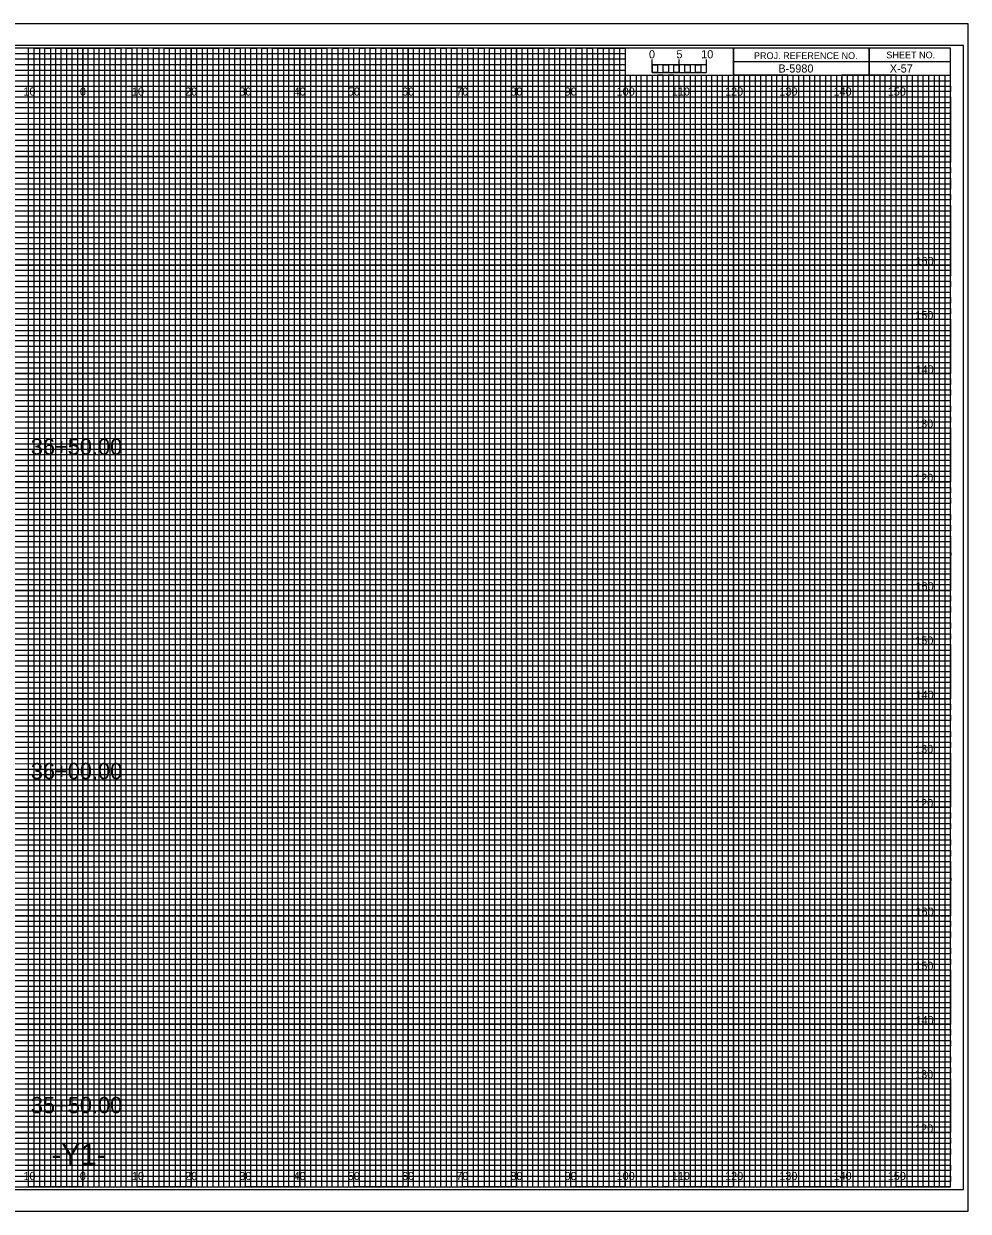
# Model space of a CAD drawing. Extents: x -13 to 323, y -5 to 4834.
# Drawn here: x 149.1 to 323.3, y 2415.5 to 2634.5 of the extents above; entities that cross this region are included whole.
import ezdxf

# ---------------------------------------------------------------- set-up
doc = ezdxf.new("R2010")
doc.units = 0
for name, color, linetype in [('Exist CMT Pavement', 7, 'Continuous'), ('Exist Cross Section Cell', 7, 'Continuous'), ('Exist XS Center Line Elevation Label', 7, 'Continuous'), ('Exist XS Ground Line', 7, 'Continuous'), ('Prop CMT Pvmt Course 1', 7, 'Continuous'), ('Prop CMT Pvmt Course 1 Wedge', 7, 'Continuous'), ('Prop CMT Pvmt Course 2', 7, 'Continuous'), ('Prop CMT Pvmt Course 2 Wedge', 7, 'Continuous'), ('Prop CMT Pvmt Course 3', 7, 'Continuous'), ('Prop CMT Pvmt Course 3 Wedge', 7, 'Continuous'), ('Prop CMT Pvmt Surface', 7, 'Continuous'), ('Prop CMT Pvmt Surface Shoulder', 7, 'Continuous'), ('Prop CMT Shld Paved Course 1', 7, 'Continuous'), ('Prop CMT Shld Paved Course 2', 7, 'Continuous'), ('Prop CMT Shld Paved Course 3', 7, 'Continuous'), ('Prop CMT Slope Grass', 7, 'Continuous'), ('Prop CMT Subgrade Earthwork', 7, 'Continuous')]:
    doc.layers.add(name, color=color, linetype=linetype)

msp = doc.modelspace()

# ---------------------------------------------------------------- linework, layer by layer
at = {"layer": 'Exist XS Center Line Elevation Label'}
for points in [[(145, 2420), (155, 2420), (155, 2630), (165, 2630), (165, 2420), (175, 2420), (175, 2630), (185, 2630), (185, 2420), (195, 2420), (195, 2630), (205, 2630), (205, 2420), (215, 2420), (215, 2630), (225, 2630), (225, 2420), (235, 2420), (235, 2630), (245, 2630), (245, 2420), (255, 2420), (255, 2630), (259.93, 2630), (260, 2630), (260, 2625), (264.99, 2625), (264.99, 2420), (275, 2420), (275, 2625), (285, 2625), (285, 2420), (295, 2420), (295, 2625), (305, 2625), (305, 2420), (315, 2420), (315, 2625)], [(0, 2625), (275, 2625)], [(0, 2605), (320, 2605), (320, 2615), (0, 2615)], [(0, 2585), (320, 2585), (320, 2595), (0, 2595)], [(0, 2565), (320, 2565), (320, 2575), (0, 2575)], [(0, 2545), (320, 2545), (320, 2555), (0, 2555)], [(0, 2525), (320, 2525), (320, 2535), (0, 2535)], [(0, 2505), (320, 2505), (320, 2515), (0, 2515)], [(0, 2485), (320, 2485), (320, 2495), (0, 2495)], [(0, 2465), (320, 2465), (320, 2475), (0, 2475)], [(0, 2445), (320, 2445), (320, 2455), (0, 2455)], [(0, 2425), (320, 2425), (320, 2435), (0, 2435)]]:
    msp.add_lwpolyline(points, dxfattribs=at)
at = {"layer": 'Exist XS Ground Line'}
for p, q in [((150, 2630), (140, 2630)), ((150, 2420), (150, 2630)), ((170, 2630), (160, 2630)), ((160, 2630), (160, 2420)), ((170, 2420), (170, 2630)), ((190, 2630), (180, 2630)), ((180, 2630), (180, 2420)), ((190, 2420), (190, 2630)), ((210, 2630), (200, 2630)), ((200, 2630), (200, 2420)), ((210, 2420), (210, 2630)), ((230, 2630), (220, 2630)), ((220, 2630), (220, 2420)), ((230, 2420), (230, 2630)), ((250, 2630), (240, 2630)), ((240, 2630), (240, 2420)), ((250, 2420), (250, 2630)), ((260, 2630), (260, 2420)), ((270, 2420), (270, 2625)), ((290, 2625), (280, 2625)), ((280, 2625), (280, 2420)), ((290, 2420), (290, 2625)), ((310, 2625), (300, 2625)), ((300, 2625), (300, 2420)), ((310, 2420), (310, 2625)), ((160, 2420), (150, 2420)), ((180, 2420), (170, 2420)), ((200, 2420), (190, 2420)), ((220, 2420), (210, 2420)), ((240, 2420), (230, 2420)), ((260, 2420), (250, 2420)), ((280, 2420), (270, 2420)), ((300, 2420), (290, 2420)), ((320, 2420), (310, 2420)), ((320, 2420), (320, 2420))]:
    msp.add_line(p, q, dxfattribs=at)
for points in [[(0, 2620), (320, 2620), (320, 2610), (0, 2610)], [(0, 2600), (320, 2600), (320, 2590), (0, 2590)], [(0, 2580), (320, 2580), (320, 2570), (0, 2570)], [(0, 2560), (320, 2560), (320, 2550), (0, 2550)], [(0, 2540), (320, 2540), (320, 2530), (0, 2530)], [(0, 2520), (320, 2520), (320, 2510), (0, 2510)], [(0, 2500), (320, 2500), (320, 2490), (0, 2490)], [(0, 2480), (320, 2480), (320, 2470), (0, 2470)], [(0, 2460), (320, 2460), (320, 2450), (0, 2450)], [(0, 2440), (320, 2440), (320, 2430), (0, 2430)]]:
    msp.add_lwpolyline(points, dxfattribs=at)
at = {"layer": 'Prop CMT Pvmt Course 1'}
for p, q in [((267, 2625), (266.01, 2625)), ((266.01, 2625), (266.01, 2420)), ((267, 2420), (267, 2625)), ((269, 2625), (268, 2625)), ((268, 2625), (268, 2420)), ((269, 2420), (269, 2625)), ((266.01, 2420), (265, 2420)), ((268, 2420), (267, 2420))]:
    msp.add_line(p, q, dxfattribs=at)
for points in [[(150, 2420), (151, 2420), (151, 2630), (152, 2630), (152, 2420)], [(152, 2420), (153, 2420), (153, 2630), (154, 2630), (154, 2420)], [(155, 2420), (156, 2420), (156, 2630), (157, 2630), (157, 2420)], [(157, 2420), (158, 2420), (158, 2630), (159, 2630), (159, 2420)], [(160, 2420), (161, 2420), (161, 2630), (162, 2630), (162, 2420)], [(162, 2420), (163, 2420), (163, 2630), (164, 2630), (164, 2420)], [(165, 2420), (166, 2420), (166, 2630), (167, 2630), (167, 2420)], [(167, 2420), (168, 2420), (168, 2630), (169, 2630), (169, 2420)], [(170, 2420), (171, 2420), (171, 2630), (172, 2630), (172, 2420)], [(172, 2420), (173, 2420), (173, 2630), (174, 2630), (174, 2420)], [(175, 2420), (176, 2420), (176, 2630), (177, 2630), (177, 2420)], [(177, 2420), (178, 2420), (178, 2630), (179, 2630), (179, 2420)], [(180, 2420), (181, 2420), (181, 2630), (182, 2630), (182, 2420)], [(182, 2420), (183, 2420), (183, 2630), (184, 2630), (184, 2420)], [(185, 2420), (186, 2420), (186, 2630), (187, 2630), (187, 2420)], [(187, 2420), (188, 2420), (188, 2630), (189, 2630), (189, 2420)], [(190, 2420), (191, 2420), (191, 2630), (192, 2630), (192, 2420)], [(192, 2420), (193, 2420), (193, 2630), (194, 2630), (194, 2420)], [(195, 2420), (196, 2420), (196, 2630), (197, 2630), (197, 2420)], [(197, 2420), (198, 2420), (198, 2630), (199, 2630), (199, 2420)], [(200, 2420), (201, 2420), (201, 2630), (202, 2630), (202, 2420)], [(202, 2420), (203, 2420), (203, 2630), (204, 2630), (204, 2420)], [(205, 2420), (206, 2420), (206, 2630), (207, 2630), (207, 2420)], [(207, 2420), (208, 2420), (208, 2630), (209, 2630), (209, 2420)], [(210, 2420), (211, 2420), (211, 2630), (212, 2630), (212, 2420)], [(212, 2420), (213, 2420), (213, 2630), (214, 2630), (214, 2420)], [(215, 2420), (216, 2420), (216, 2630), (217, 2630), (217, 2420)], [(217, 2420), (218, 2420), (218, 2630), (219, 2630), (219, 2420)], [(220, 2420), (221, 2420), (221, 2630), (222, 2630), (222, 2420)], [(222, 2420), (223, 2420), (223, 2630), (224, 2630), (224, 2420)], [(225, 2420), (226, 2420), (226, 2630), (227, 2630), (227, 2420)], [(227, 2420), (228, 2420), (228, 2630), (229, 2630), (229, 2420)], [(230, 2420), (231, 2420), (231, 2630), (232, 2630), (232, 2420)], [(232, 2420), (233, 2420), (233, 2630), (234, 2630), (234, 2420)], [(235, 2420), (236, 2420), (236, 2630), (237, 2630), (237, 2420)], [(237, 2420), (238, 2420), (238, 2630), (239, 2630), (239, 2420)], [(240, 2420), (241, 2420), (241, 2630), (242, 2630), (242, 2420)], [(242, 2420), (243, 2420), (243, 2630), (244, 2630), (244, 2420)], [(245, 2420), (246, 2420), (246, 2630), (247, 2630), (247, 2420)], [(247, 2420), (248, 2420), (248, 2630), (249, 2630), (249, 2420)], [(250, 2420), (251, 2420), (251, 2630), (252, 2630), (252, 2420)], [(252, 2420), (253, 2420), (253, 2630), (254, 2630), (254, 2420)], [(255, 2420), (256, 2420), (256, 2630), (257, 2630), (257, 2420)], [(257, 2420), (258, 2420), (258, 2630), (259, 2630), (259, 2420)], [(260, 2420), (261, 2420), (261, 2625), (262.02, 2625), (262.02, 2420)], [(262, 2420), (263, 2420), (263, 2625), (263.99, 2625), (263.99, 2420)], [(270, 2420), (270.98, 2420), (270.98, 2625), (272, 2625), (272, 2420)], [(272, 2420), (273, 2420), (273, 2625), (274.05, 2625), (274.05, 2420)], [(275, 2420), (276, 2420), (276, 2625), (277, 2625), (277, 2420)], [(277, 2420), (278, 2420), (278, 2625), (279, 2625), (279, 2420)], [(280, 2420), (281, 2420), (281, 2625), (282, 2625), (282, 2420)], [(282, 2420), (283, 2420), (283, 2625), (284, 2625), (284, 2420)], [(285, 2420), (286, 2420), (286, 2625), (287, 2625), (287, 2420)], [(287, 2420), (288, 2420), (288, 2625), (289, 2625), (289, 2420)], [(290, 2420), (291, 2420), (291, 2625), (292, 2625), (292, 2420)], [(292, 2420), (293, 2420), (293, 2625), (294, 2625), (294, 2420)], [(295, 2420), (296, 2420), (296, 2625), (297, 2625), (297, 2420)], [(297, 2420), (298, 2420), (298, 2625), (299, 2625), (299, 2420)], [(300, 2420), (301, 2420), (301, 2625), (302, 2625), (302, 2420)], [(302, 2420), (303, 2420), (303, 2625), (304, 2625), (304, 2420)], [(305, 2420), (306, 2420), (306, 2625), (307, 2625), (307, 2420)], [(307, 2420), (308, 2420), (308, 2625), (309, 2625), (309, 2420)], [(310, 2420), (311, 2420), (311, 2625), (312, 2625), (312, 2420)], [(312, 2420), (313, 2420), (313, 2625), (314, 2625), (314, 2420)], [(315, 2420), (316, 2420), (316, 2625), (317, 2625), (317, 2420)], [(317, 2420), (318, 2420), (318, 2625), (319, 2625), (319, 2420)]]:
    msp.add_lwpolyline(points, dxfattribs=at)
at = {"layer": 'Prop CMT Pvmt Course 2'}
for p, q in [((323.3, 2634.5), (-13.4, 2634.5)), ((-13.4, 2415.5), (323.3, 2415.5))]:
    msp.add_line(p, q, dxfattribs=at)
at = {"layer": 'Prop CMT Pvmt Surface Shoulder'}
for p, q in [((305, 2630), (305, 2625)), ((305, 2625), (305, 2630)), ((280, 2627.5), (280, 2625)), ((320, 2627.49), (280, 2627.49)), ((280, 2625), (320, 2625))]:
    msp.add_line(p, q, dxfattribs=at)
for points in [[(320, 2630), (0, 2630), (0, 2420), (320, 2420)], [(280, 2630), (260, 2630), (260, 2625.03), (280, 2625.03)], [(320, 2630), (280, 2630), (280, 2625), (320, 2625)]]:
    msp.add_lwpolyline(points, close=True, dxfattribs=at)
at = {"layer": 'Prop CMT Shld Paved Course 1'}
msp.add_lwpolyline([(-13.4, 2415.5), (323.3, 2415.5), (323.3, 2634.5), (-13.4, 2634.5)], close=True, dxfattribs=at)
at = {"layer": 'Prop CMT Shld Paved Course 2'}
msp.add_lwpolyline([(-10.8, 2419.5), (322.4, 2419.5), (322.4, 2630.5), (-10.8, 2630.5)], close=True, dxfattribs=at)
at = {"layer": 'Prop CMT Shld Paved Course 3'}
for p, q in [((150, 2420), (150, 2630)), ((160, 2420), (160, 2630)), ((170, 2420), (170, 2630)), ((180, 2420), (180, 2630)), ((190, 2420), (190, 2630)), ((200, 2420), (200, 2630)), ((210, 2420), (210, 2630)), ((220, 2420), (220, 2630)), ((230, 2420), (230, 2630)), ((240, 2420), (240, 2630)), ((250, 2420), (250, 2630)), ((260, 2420), (260, 2624.69)), ((270, 2420), (270, 2624.69)), ((280, 2420), (280, 2624.69)), ((290, 2420), (290, 2624.69)), ((300, 2420), (300, 2624.69)), ((310, 2420), (310, 2624.69)), ((0, 2620), (320, 2620)), ((0, 2610), (320, 2610)), ((0, 2600), (320, 2600)), ((0, 2590), (320, 2590)), ((0, 2580), (320, 2580)), ((0, 2570), (320, 2570)), ((0, 2560), (320, 2560)), ((0, 2550), (320, 2550)), ((0, 2540), (320, 2540)), ((0, 2530), (320, 2530)), ((0, 2520), (320, 2520)), ((0, 2510), (320, 2510)), ((0, 2500), (320, 2500)), ((0, 2490), (320, 2490)), ((0, 2480), (320, 2480)), ((0, 2470), (320, 2470)), ((0, 2460), (320, 2460)), ((0, 2450), (320, 2450)), ((0, 2440), (320, 2440)), ((0, 2430), (320, 2430))]:
    msp.add_line(p, q, dxfattribs=at)
at = {"layer": 'Prop CMT Slope Grass'}
for p, q in [((0, 2629), (260, 2629)), ((260, 2629), (260, 2627.98)), ((260, 2627.98), (0, 2627.98)), ((0, 2627), (260, 2627)), ((260, 2625.89), (0, 2625.89)), ((260, 2627), (260, 2625.89)), ((0, 2624), (320, 2624))]:
    msp.add_line(p, q, dxfattribs=at)
for points in [[(0, 2623), (270, 2623), (320, 2623), (320, 2622), (0, 2622)], [(0, 2621), (320, 2621), (320, 2619), (0, 2619)], [(0, 2618), (320, 2618), (320, 2617), (0, 2616.98)], [(0, 2616), (320, 2616), (320, 2614), (0, 2614)], [(0, 2613), (320, 2613), (320, 2612), (0, 2612)], [(0, 2611), (320, 2611), (320, 2609), (0, 2609)], [(0, 2608), (320, 2608), (320, 2607), (0, 2607)], [(0, 2606), (320, 2606), (320, 2604), (0, 2604)], [(0, 2603), (320, 2603), (320, 2602), (0, 2602)], [(0, 2601), (320, 2601), (320, 2599), (0, 2599)], [(0, 2598), (320, 2598), (320, 2597), (0, 2597)], [(0, 2596), (320, 2596), (320, 2593.95), (320, 2593), (320, 2592), (0, 2592)], [(0, 2594), (320, 2594), (320, 2593), (0, 2593)], [(0, 2591), (320, 2591), (320, 2589), (0, 2589.03)], [(0, 2589.03), (320, 2589), (320, 2588), (0, 2588)], [(0, 2587), (320, 2587), (320, 2586), (0, 2586)], [(0, 2584), (320, 2584), (320, 2583), (0, 2583)], [(0, 2582), (320, 2582), (320, 2581), (0, 2581)], [(-0.07, 2578.89), (320, 2578.89), (320, 2577.88), (-0.07, 2577.88)], [(0, 2577), (320, 2577), (320, 2576), (0, 2576)], [(0, 2574), (320, 2574), (320, 2573), (0, 2573)], [(0, 2572), (320, 2572), (320, 2571), (0, 2571)], [(0, 2569), (320, 2569), (320, 2568), (0, 2568)], [(0, 2567), (320, 2567), (320, 2566), (0, 2566)], [(0, 2564), (320, 2564), (320, 2563), (0, 2563)], [(0, 2562), (320, 2562), (320, 2561), (0, 2561)], [(0, 2559), (320, 2559), (319.99, 2557.98), (0, 2558)], [(0, 2557), (320, 2557), (320, 2556), (0, 2556)], [(0, 2554), (320, 2554), (320, 2553), (0, 2553)], [(0, 2552), (320, 2552), (320, 2551), (0, 2551)], [(0, 2549), (320, 2549), (320, 2548), (0, 2548)], [(0, 2547), (320, 2547), (320, 2546), (0, 2546)], [(0, 2544), (320, 2544), (320, 2543), (0, 2543)], [(0, 2542), (320, 2542), (320, 2541), (0, 2541)], [(0, 2539), (320, 2539), (320, 2538), (0, 2538)], [(0, 2536.99), (320.07, 2536.91), (320, 2536), (0, 2536)], [(0, 2534), (320, 2534), (320, 2533), (0, 2533)], [(0, 2532), (320, 2532), (320, 2531), (0, 2531)], [(0, 2529), (320, 2529), (320, 2528), (0, 2528)], [(0, 2527), (320, 2527), (320, 2526), (0, 2526)], [(0, 2524), (320, 2524), (320, 2523), (0, 2523)], [(0, 2522), (320, 2522), (320, 2521), (0, 2521)], [(0, 2519), (320, 2519), (320, 2518), (0, 2518)], [(0, 2517), (320, 2517), (320, 2516), (0, 2516)], [(0, 2514), (320, 2514), (320, 2513), (0, 2513)], [(0, 2512), (320, 2512), (320, 2511), (0, 2511)], [(0, 2509), (320, 2509), (320, 2508), (0, 2508)], [(0, 2507), (320, 2507), (320, 2506), (0, 2506)], [(0, 2504), (320, 2504), (320, 2503), (0, 2503)], [(0, 2502), (320, 2502), (320, 2501), (0, 2501)], [(0, 2499), (320, 2499), (319.99, 2497.98), (0, 2498)], [(0, 2497), (320, 2497), (320, 2496), (0, 2496)], [(0, 2494), (320, 2494), (320, 2493), (0, 2493)], [(0, 2492), (320, 2492), (320, 2491), (0, 2491)], [(0, 2489), (320, 2489), (320, 2488), (0, 2488)], [(0, 2487), (320, 2487), (320, 2486), (0, 2486)], [(0, 2484), (320, 2484), (320, 2483), (0, 2483)], [(0, 2482), (320, 2482), (320, 2481), (0, 2481)], [(0, 2479), (320, 2479), (320, 2478), (0, 2478)], [(0, 2476.99), (320.07, 2476.91), (320, 2476), (0, 2476)], [(0, 2474), (320, 2474), (320, 2473), (0, 2473)], [(0, 2472), (320, 2472), (320, 2471), (0, 2471)], [(0, 2469), (320, 2469), (320, 2468), (0, 2468)], [(0, 2467), (320, 2467), (320, 2466), (0, 2466)], [(0, 2464), (320, 2464), (320, 2463), (0, 2463)], [(0, 2462), (320, 2462), (320, 2461), (0, 2461)], [(0, 2459), (320, 2459), (320, 2458), (0, 2458)], [(0, 2457), (320, 2457), (320, 2456), (0, 2456)], [(0, 2454), (320, 2454), (320, 2453), (0, 2453)], [(0, 2452), (320, 2452), (320, 2451), (0, 2451)], [(0, 2449), (320, 2449), (320, 2448), (0, 2448)], [(0, 2447), (320, 2447), (320, 2446), (0, 2446)], [(0, 2444), (320, 2444), (320, 2443), (0, 2443)], [(0, 2442), (320, 2442), (320, 2441), (0, 2441)], [(0, 2439), (320, 2439), (320, 2438), (0, 2438)], [(0, 2437), (320, 2437), (320, 2436), (0, 2436)], [(0, 2434), (320, 2434), (320, 2433), (0, 2433)], [(0, 2432), (320, 2432), (320, 2431), (0, 2431)], [(0, 2429), (320, 2429), (320, 2428), (0, 2428)], [(0, 2427), (320, 2427), (320, 2426), (0, 2426)], [(0, 2424), (320, 2424), (320, 2423), (0, 2423)], [(0, 2422), (320, 2422), (320, 2421), (0, 2421)]]:
    msp.add_lwpolyline(points, dxfattribs=at)
at = {"layer": 'Prop CMT Subgrade Earthwork'}
for p, q in [((265, 2625.49), (265, 2627.9)), ((265, 2626.9), (265, 2627.9)), ((270, 2625.49), (270, 2627.9)), ((275, 2625.49), (275, 2627.9)), ((275, 2626.9), (275, 2627.9))]:
    msp.add_line(p, q, dxfattribs=at)
for points in [[(275, 2626.9), (265, 2626.9), (265, 2625.49), (275, 2625.49)], [(265, 2626.9), (266, 2626.9), (266, 2625.49), (265, 2625.49)], [(267, 2626.9), (268, 2626.9), (268, 2625.49), (267, 2625.49)], [(269, 2626.9), (270, 2626.9), (270, 2625.49), (269, 2625.49)], [(271, 2626.9), (272, 2626.9), (272, 2625.49), (271, 2625.49)], [(273, 2626.9), (274, 2626.9), (274, 2625.49), (273, 2625.49)]]:
    msp.add_lwpolyline(points, close=True, dxfattribs=at)

# ---------------------------------------------------------------- texts
at = {"layer": 'Exist CMT Pavement'}
msp.add_text('-Y1-', height=4, dxfattribs=at).set_placement((154.21, 2424))
at = {"layer": 'Exist Cross Section Cell'}
for s, p in [('10', (149.04, 2621.25)), ('0', (159.45, 2621.25)), ('0', (159.45, 2621.25)), ('10', (169.04, 2621.25)), ('20', (178.86, 2621.25)), ('30', (188.86, 2621.25)), ('40', (198.86, 2621.25)), ('50', (208.86, 2621.25)), ('60', (218.86, 2621.25)), ('70', (228.86, 2621.25)), ('80', (238.86, 2621.25)), ('90', (248.86, 2621.25)), ('100', (258.44, 2621.25)), ('110', (268.62, 2621.25)), ('120', (278.44, 2621.25)), ('130', (288.44, 2621.25)), ('140', (298.44, 2621.25)), ('150', (308.44, 2621.25)), ('10', (149.04, 2421.25)), ('0', (159.45, 2421.25)), ('0', (159.45, 2421.25)), ('10', (169.04, 2421.25)), ('20', (178.86, 2421.25)), ('30', (188.86, 2421.25)), ('40', (198.86, 2421.25)), ('50', (208.86, 2421.25)), ('60', (218.86, 2421.25)), ('70', (228.86, 2421.25)), ('80', (238.86, 2421.25)), ('90', (248.86, 2421.25)), ('100', (258.44, 2421.25)), ('110', (268.62, 2421.25)), ('120', (278.44, 2421.25)), ('130', (288.44, 2421.25)), ('140', (298.44, 2421.25)), ('150', (308.44, 2421.25))]:
    msp.add_text(s, height=1.5, dxfattribs=at).set_placement(p)
at = {"layer": 'Prop CMT Pvmt Course 1 Wedge'}
for s, p in [('36+50.00', (150.41, 2555.01)), ('36+00.00', (150.41, 2495.18)), ('35+50.00', (150.41, 2433.58))]:
    msp.add_text(s, height=3, dxfattribs=at).set_placement(p)
at = {"layer": 'Prop CMT Pvmt Course 2 Wedge'}
msp.add_text('X-57', height=1.5, dxfattribs=at).set_placement((308.83, 2625.5))
at = {"layer": 'Prop CMT Pvmt Course 3'}
for s, p in [('160', (313.57, 2590)), ('150', (313.52, 2580)), ('140', (313.57, 2570)), ('130', (313.49, 2560)), ('120', (313.5, 2550)), ('160', (313.57, 2530)), ('150', (313.52, 2520)), ('140', (313.57, 2510)), ('130', (313.49, 2500)), ('120', (313.5, 2490)), ('160', (313.57, 2470)), ('150', (313.52, 2460)), ('140', (313.57, 2450)), ('130', (313.49, 2440)), ('120', (313.5, 2430))]:
    msp.add_text(s, height=1.5, dxfattribs=at).set_placement(p)
at = {"layer": 'Prop CMT Pvmt Course 3 Wedge'}
msp.add_text('B-5980', height=1.5, dxfattribs=at).set_placement((288.28, 2625.5))
at = {"layer": 'Prop CMT Pvmt Surface'}
for s, p in [('5', (269.47, 2628.12)), ('10', (274.04, 2628.12))]:
    msp.add_text(s, height=1.5, dxfattribs=at).set_placement(p)
at = {"layer": 'Prop CMT Pvmt Surface Shoulder'}
for s, p in [('PROJ. REFERENCE NO.', (283.77, 2627.99)), ('SHEET NO.', (308.19, 2628.12))]:
    msp.add_text(s, height=1.25, dxfattribs=at).set_placement(p)
at = {"layer": 'Prop CMT Subgrade Earthwork'}
msp.add_text('0', height=1.5, dxfattribs=at).set_placement((264.41, 2628.12))

doc.saveas('drawing.dxf')
